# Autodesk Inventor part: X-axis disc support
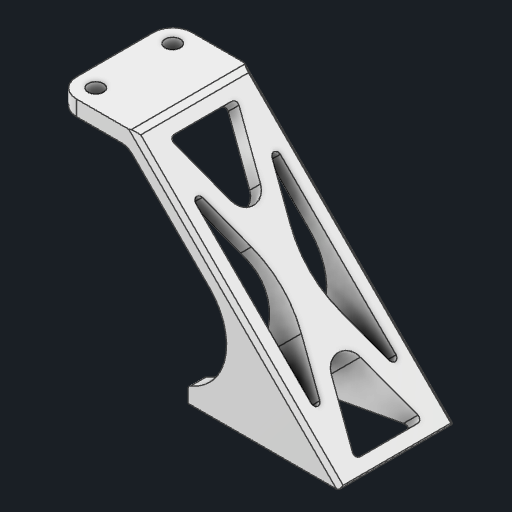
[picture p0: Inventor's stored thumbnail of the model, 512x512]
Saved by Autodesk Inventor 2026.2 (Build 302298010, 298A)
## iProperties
Created: 2026-04
Part Number: X-axis disc support
Material: PBT 플라스틱
Document SubType Name: Modeling
Designer: work
Density: 1.31 g/cm^3
Appearance: 매끄러움 - 흰색
Author: work
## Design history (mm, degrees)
sketch "스케치1"
  geometry: L1 (0, 10)-(0, -10); L2 (-5, 10)-(-5, -10); L3 (5, -10)-(5, 10); L4 (0, 15)-(-15, 15); L5 (-15, 15)-(-15, -15); L6 (-15, -15)-(0, -15); L7 (0, -15)-(0, 15); C1 r 2 at (0, 10); C2 r 2 at (0, -10); A1 r 5 centre (0, 10) between (5, 10) and (-5, 10); A2 r 5 centre (0, -10) between (-5, -10) and (5, -10); 2 further points
  constraints: 16 end point, 5 point on circle, 4 centre point, 4 tangent, 3 parallel, 2 coincident, 1 horizontal, 1 midpoint, 1 perpendicular, 1 vertical
  dimensions: "d0" = 10 distance of point (0, 0) L1.end; "d1" = 10 diameter of A2; "d2" = 4 diameter of C1; "d3" = 4 diameter of C2; "d4" = 15 distance of L6.end L5.end; "d5" = 30 distance of L4.end L5.end
extrude "돌출1" new body sketch "스케치1" distance "d6" = 4; taper "d7" = 0 deg
sketch "스케치2"
  geometry: L1 (15, 0)-(15, 4) reference; L2 (15, 4)-(69, -50); L3 (69, -50)-(29, -50); L4 (29, -50)-(29, -46); L5 (29, -46)-(59.343, -46); L6 (59.343, -46)-(13.343, 0); L7 (0, 0)-(15, 0) reference; L8 (15, 0)-(15, 4) reference; L9 (0, 4)-(15, 4) reference; L10 (0, 0)-(0, 4) reference; L11 (0, 0)-(15, 0) reference; 2 further points
  constraints: 10 end point, 3 perpendicular, 1 parallel, 1 point on line
  dimensions: "d8" = 4 distance between parallel lines of L6 L2; "d9" = 135 deg angle of L7 L6; "d10" = 50 distance between parallel lines of L7 L3; "d11" = 4 distance between parallel lines of L3 L5; "d12" = 40 distance from line of L2.end L4
extrude "돌출2" join sketch "스케치2" stored distance "d13" = 4; taper "d14" = 0 deg
fillet "모깎기1" dims "d15" = 15
fillet "모깎기2" dims "d16" = 4
chamfer "모따기1" distance "d17" = 1; stored, may be unused: second distance "d18" = 2, angle "d19" = 45 deg
sketch "스케치3"
  geometry: L1 (0, 0)-(-74.368, 0) reference; L2 (0, 28)-(0, 0) reference; L3 (-74.368, 28)-(0, 28) reference; L4 (-74.368, 0)-(-74.368, 28) reference; L5 (-3, 3)-(-71.368, 3); L6 (-71.368, 3)-(-71.368, 25); L7 (-71.368, 25)-(-3, 25); L8 (-3, 25)-(-3, 3); L9 (-3, 25)-(-71.368, 3); L10 (-71.368, 25)-(-3, 3); L11 (-64.838, 3)-(-3, 22.899); L12 (-3, 5.101)-(-64.838, 25); L13 (-9.529, 25)-(-71.368, 5.101); L14 (-9.529, 3)-(-71.368, 22.899); A1 r 4 centre (-17.596, 14) between (-18.822, 17.808) and (-18.822, 10.192); A2 r 4 centre (-56.771, 14) between (-55.546, 10.192) and (-55.546, 17.808); A3 r 30 centre (-37.184, -19.616) between (-27.994, 8.942) and (-46.373, 8.942); A4 r 30 centre (-37.184, 47.616) between (-46.373, 19.058) and (-27.994, 19.058); 1 further point
  constraints: 20 end point, 16 point on line, 8 point on circle, 8 tangent, 4 centre point, 4 parallel, 3 other
  dimensions: "d20" = 3 distance between parallel lines of L2 L8; "d22" = 4 distance between parallel lines of L12 L14; "d23" = 2 distance between parallel lines of L14 L10; "d24" = 2 distance between parallel lines of L13 L9; "d25" = 2 distance between parallel lines of L9 L11; "d26" = 4 radius of A1; "d27" = 4 radius of A2; "d28" = 30 radius of A4; "d29" = 30 radius of A3
extrude "돌출3" cut sketch "스케치3" extent not by distance; stored distance "d30" = 0; taper "d31" = 0 deg
fillet "모깎기3" dims "d32" = 1
node "솔리드1"
node "투영된 루프1"
node "투영된 루프2"
